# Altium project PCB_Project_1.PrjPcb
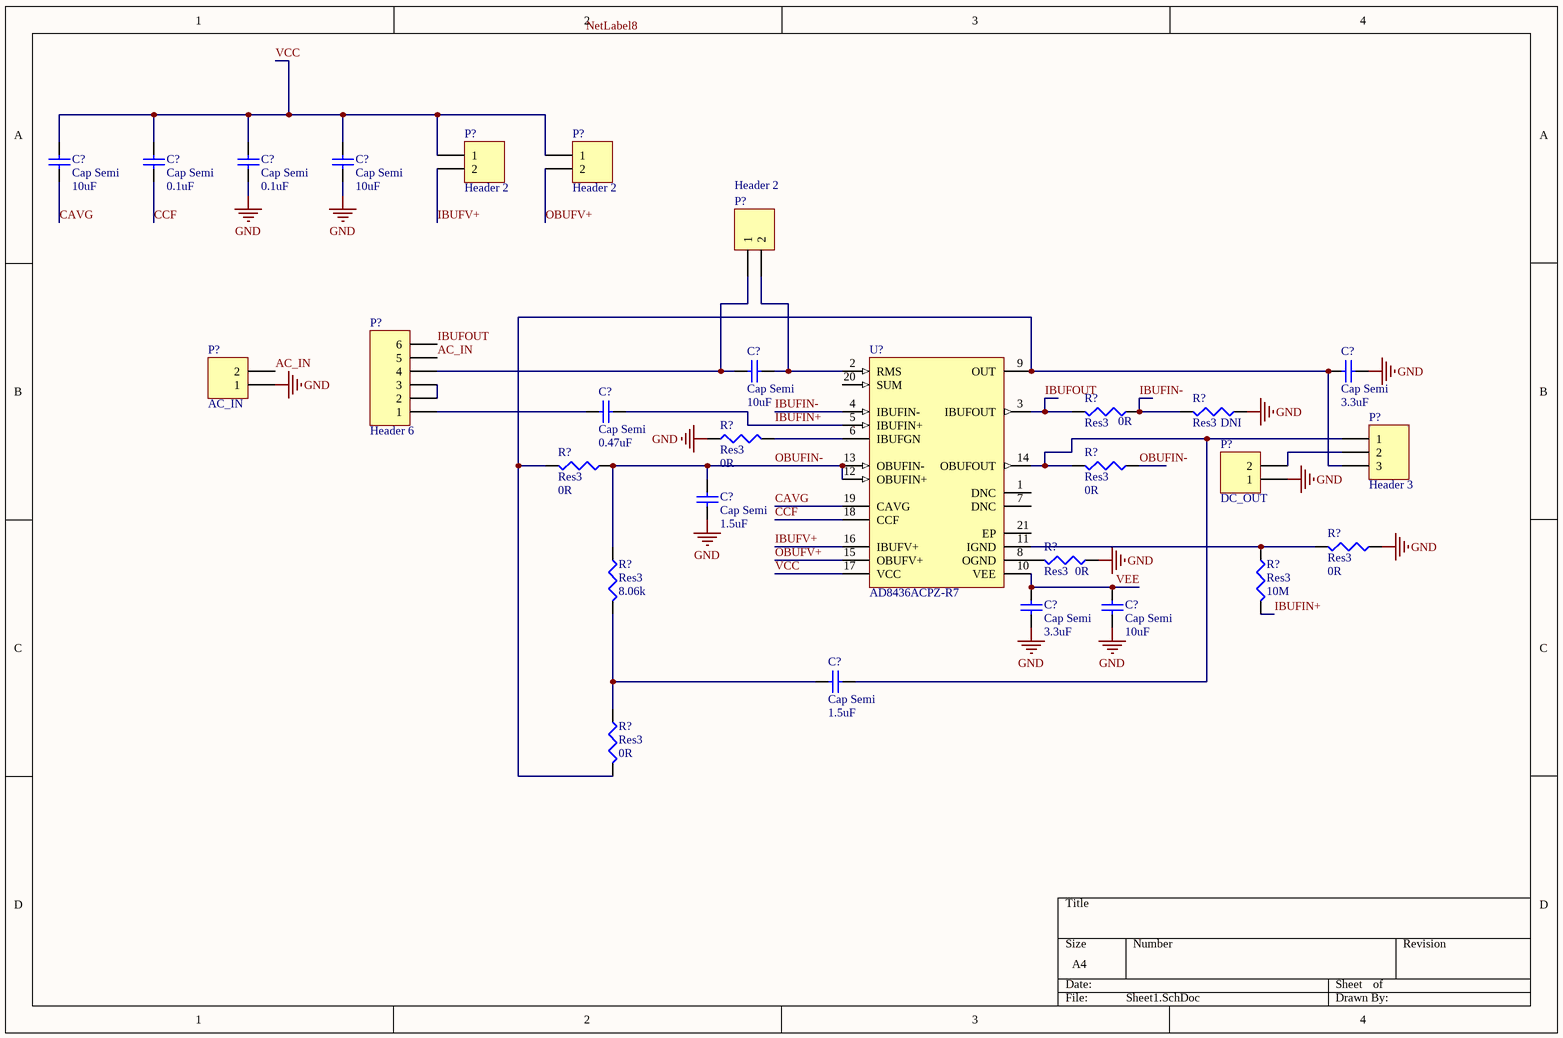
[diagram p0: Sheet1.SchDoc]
1 sheet, 29 parts. Net scope: global (net labels, ports and power ports of the same name join across sheets).

## Sheet Sheet1.SchDoc
size A4

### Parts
(Parts that share a designator on the sheet are numbered #1, #2 ... from top to bottom, then left to right.)
C?#1  Cap Semi  value 10uF  [C1206]
C?#2  Cap Semi  value 0.1uF  [C1206]
C?#3  Cap Semi  value 0.1uF  [C1206]
C?#4  Cap Semi  value 10uF  [C1206]
C?#5  Cap Semi  value 10uF  [C1206]
C?#6  Cap Semi  value 3.3uF  [C1206]
C?#7  Cap Semi  value 0.47uF  [C1206]
C?#8  Cap Semi  value 1.5uF  [C1206]
C?#9  Cap Semi  value 3.3uF  [C1206]
C?#10  Cap Semi  value 10uF  [C1206]
C?#11  Cap Semi  value 1.5uF  [C1206]
P?#1  Header 2  [HDR1X2]
P?#2  Header 2  [HDR1X2]
P?#3  Header 2  [HDR1X2]
P?#4  AC_IN  [HDR1X2]
P?#5  Header 6  [HDR1X6]
P?#6  Header 3  [HDR1X3]
P?#7  DC_OUT  [HDR1X2]
R?#1  Res3  value 0R  [J1-0603]
R?#2  Res3  value 0R  [J1-0603]
R?#3  Res3  value DNI  [J1-0603]
R?#4  Res3  value 0R  [J1-0603]
R?#5  Res3  value 0R  [J1-0603]
R?#6  Res3  value 8.06k  [J1-0603]
R?#7  Res3  value 10M  [J1-0603]
R?#8  Res3  value 0R  [J1-0603]
R?#9  Res3  value 0R  [J1-0603]
R?#10  Res3  value 0R  [J1-0603]
U?  AD8436ACPZ-R7  [ADI-CP-20-10_M]

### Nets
GND: C?#3.1 C?#4.1 C?#6.2 C?#8.1 C?#9.2 C?#10.2 P?#4.1 P?#7.1 R?#1.1 R?#3.1 R?#8.1 R?#9.1
AC_IN: P?#4.2 P?#5.5
CAVG: C?#1.1 U?.19(CAVG)
CCF: C?#2.1 U?.18(CCF)
IBUFIN+: C?#7.2 R?#7.2 U?.5(IBUFIN+)
IBUFIN-: R?#2.1 R?#3.2 U?.4(IBUFIN-)
IBUFOUT: P?#5.6 R?#2.2 U?.3(IBUFOUT)
IBUFV+: P?#1.2 U?.16(IBUFV+)
OBUFIN-: C?#8.2 R?#4.1 R?#5.1 R?#6.1 U?.12(OBUFIN+) U?.13(OBUFIN-)
OBUFV+: P?#2.2 U?.15(OBUFV+)
VCC: C?#1.2 C?#2.2 C?#3.2 C?#4.2 P?#1.1 P?#2.1 U?.17(VCC)
VEE: C?#9.1 C?#10.1 U?.10(VEE)
NetC?#5_1: C?#5.1 P?#3.1 P?#5.4
NetC?#5_2: C?#5.2 P?#3.2 U?.2(RMS)
NetC?#6_1: C?#6.1 P?#6.3 R?#4.2 R?#10.2 U?.9(OUT)
NetC?#7_1: C?#7.1 P?#5.1
NetC?#11_1: C?#11.1 P?#6.1 R?#5.2 U?.14(OBUFOUT)
NetC?#11_2: C?#11.2 R?#6.2 R?#10.1
NetP?#5_2: P?#5.2 P?#5.3
NetP?#6_2: P?#6.2 P?#7.2
NetR?#1_2: R?#1.2 U?.6(IBUFGN)
NetR?#7_1: R?#7.1 R?#8.2 U?.11(IGND)
NetR?#9_2: R?#9.2 U?.8(OGND)

Not connected (* = marked no-connect by the designer): U? 1(DNC) 7(DNC) 20(SUM) 21(EP)

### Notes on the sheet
- Labels drawn without touching a wire or pin: NetLabel8

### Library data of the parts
C?#1-C?#11 = Cap Semi: Capacitor (Semiconductor SIM Model)
P?#1-P?#4 P?#7 = Header 2: Header, 2-Pin
P?#5 = Header 6: Header, 6-Pin
P?#6 = Header 3: Header, 3-Pin
R?#1-R?#10 = Res3: Resistor
U? = CMP-0527-00003-3: Low Cost, Low Power, True RMS-to-DC Converter, 4.8 to 36 V Single Supply, -40 to 125 degC, 20-Pin QFN (CP-20-10); Manufacturer: Analog Devices; -3dB Bandwidth: 950 KHz; Max Vin (V-rms): 3 V rms; V Span (min): 4.8 V; Supply Current: 300 uA; V Span (max): 36 V; Error (%@ CF: 3)=0.5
